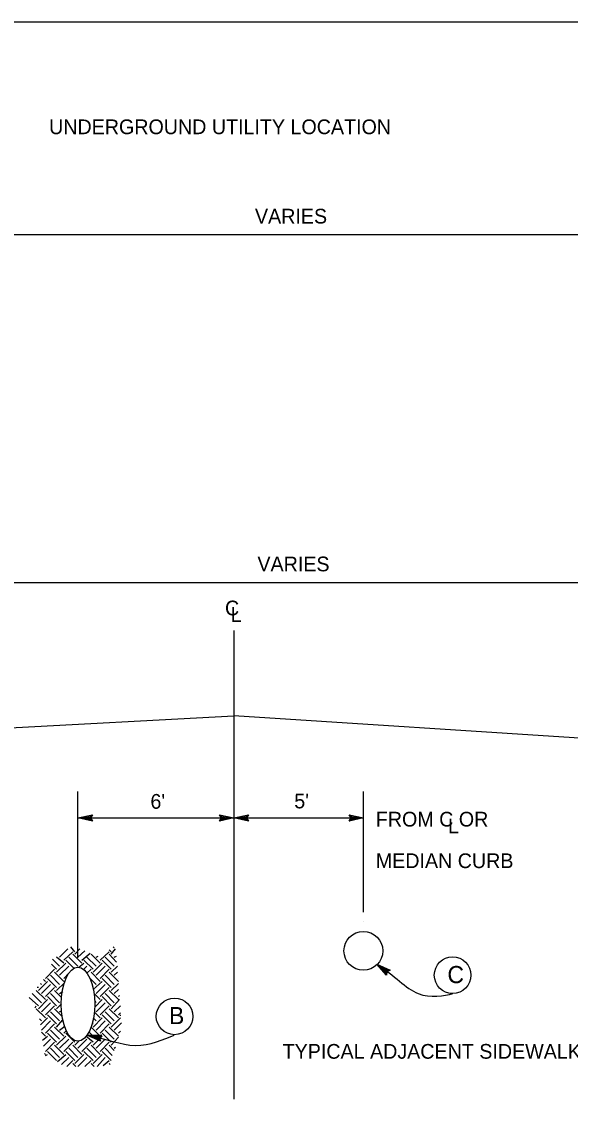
# Model space of a CAD drawing. Extents: x -119017 to -116080, y -104449 to -102845.
# Drawn here: x -118523 to -118299.2, y -103289.7 to -102845.2 of the extents above; entities that cross this region are included whole.
import ezdxf

# ---------------------------------------------------------------- set-up
doc = ezdxf.new("R2010")
doc.units = 0
for name, color, linetype in [('Default', 7, 'Continuous'), ('G-MARK', 7, 'Continuous'), ('G-TEXT', 7, 'Continuous'), ('Misc CnstDet(22)', 7, 'Continuous')]:
    doc.layers.add(name, color=color, linetype=linetype)

msp = doc.modelspace()

# ---------------------------------------------------------------- linework, layer by layer
at = {"layer": 'Default'}
msp.add_lwpolyline([(-119016.83, -102845.16), (-117223.08, -102845.16), (-117223.08, -104295.16), (-119016.83, -104295.16)], close=True, dxfattribs=at)
at = {"layer": 'G-MARK'}
for p, q in [((-118125.99, -102932.03), (-118744.83, -102932.03)), ((-118624.48, -103073.82), (-118229.29, -103073.82)), ((-118500.05, -103226.77), (-118500.05, -103158.98)), ((-118383.48, -103208.17), (-118383.48, -103158.98)), ((-118500.05, -103169.72), (-118436.44, -103169.72)), ((-118436.44, -103169.72), (-118383.48, -103169.72))]:
    msp.add_line(p, q, dxfattribs=at)
for centre in [(-118347.19, -103233.85), (-118460.65, -103250.64)]:
    msp.add_circle(centre, 7.47, dxfattribs=at)
for points in [[(-118378.15, -103229.35), (-118370.71, -103233.9), (-118362.03, -103244.65), (-118350.46, -103242.17), (-118347.15, -103241.34)], [(-118496.38, -103258.29), (-118488.53, -103259.53), (-118476.54, -103265.32), (-118464.96, -103259.95), (-118460.83, -103258.29)]]:
    msp.add_open_spline(points, degree=3, dxfattribs=at)
at = {"layer": 'G-TEXT'}
for points in [[(-118494.15, -103171.04), (-118500.05, -103169.72), (-118494.15, -103168.42), (-118494.36, -103168.76), (-118498.68, -103169.72), (-118494.36, -103170.69), (-118494.57, -103170.34), (-118497.33, -103169.73), (-118494.57, -103169.11), (-118494.78, -103169.46), (-118495.97, -103169.73), (-118494.77, -103170), (-118494.94, -103169.72), (-118494.15, -103168.42), (-118494.94, -103169.72)], [(-118442.3, -103168.41), (-118436.39, -103169.72), (-118442.3, -103171.03), (-118442.09, -103170.68), (-118437.76, -103169.73), (-118442.09, -103168.76), (-118441.88, -103169.1), (-118439.11, -103169.72), (-118441.88, -103170.34), (-118441.67, -103169.99), (-118440.47, -103169.72), (-118441.67, -103169.45), (-118441.51, -103169.72), (-118442.3, -103171.03), (-118441.51, -103169.72)], [(-118430.49, -103171.04), (-118436.39, -103169.72), (-118430.49, -103168.42), (-118430.7, -103168.76), (-118435.02, -103169.72), (-118430.7, -103170.69), (-118430.9, -103170.34), (-118433.67, -103169.73), (-118430.91, -103169.11), (-118431.12, -103169.46), (-118432.31, -103169.73), (-118431.11, -103170), (-118431.27, -103169.72), (-118430.49, -103168.42), (-118431.27, -103169.72)], [(-118389.38, -103168.41), (-118383.48, -103169.72), (-118389.39, -103171.03), (-118389.18, -103170.68), (-118384.85, -103169.73), (-118389.18, -103168.76), (-118388.97, -103169.1), (-118386.2, -103169.72), (-118388.97, -103170.34), (-118388.75, -103169.99), (-118387.56, -103169.72), (-118388.76, -103169.45), (-118388.6, -103169.72), (-118389.39, -103171.03), (-118388.6, -103169.72)], [(-118374.15, -103233.89), (-118378.15, -103229.35), (-118372.6, -103231.76), (-118372.98, -103231.92), (-118377.04, -103230.16), (-118374.11, -103233.48), (-118374.07, -103233.08), (-118375.95, -103230.95), (-118373.35, -103232.08), (-118373.73, -103232.24), (-118374.85, -103231.75), (-118374.04, -103232.67), (-118374.01, -103232.36), (-118372.6, -103231.76), (-118374.01, -103232.36)], [(-118490.83, -103260.71), (-118496.38, -103258.29), (-118490.33, -103258.13), (-118490.61, -103258.43), (-118495.04, -103258.55), (-118490.97, -103260.32), (-118491.11, -103259.94), (-118493.71, -103258.81), (-118490.88, -103258.73), (-118491.15, -103259.03), (-118492.38, -103259.07), (-118491.25, -103259.56), (-118491.36, -103259.26), (-118490.33, -103258.13), (-118491.36, -103259.26)]]:
    msp.add_lwpolyline(points, close=True, dxfattribs=at)
at = {"layer": 'Misc CnstDet(22)'}
for p, q in [((-118436.44, -103093.35), (-118436.44, -103284.34)), ((-118620.81, -103138), (-118436.44, -103128.08)), ((-118233.06, -103141.3), (-118436.44, -103128.08)), ((-118436.39, -103169.31), (-118436.39, -103169.31)), ((-118436.39, -103169.31), (-118436.39, -103169.31)), ((-118436.39, -103169.72), (-118436.39, -103169.72)), ((-118383.48, -103169.72), (-118383.48, -103169.72)), ((-118383.48, -103211.89), (-118383.48, -103211.89)), ((-118507.54, -103226.46), (-118504.24, -103223.15)), ((-118505.89, -103227.7), (-118502.17, -103224.39)), ((-118501.34, -103224.39), (-118503, -103222.33)), ((-118501.34, -103225.22), (-118499.28, -103223.15)), ((-118500.1, -103222.74), (-118500.1, -103222.74)), ((-118500.1, -103226.46), (-118497.21, -103223.98)), ((-118498.45, -103227.7), (-118495.14, -103224.81)), ((-118491.01, -103227.7), (-118487.29, -103224.39)), ((-118486.46, -103224.39), (-118487.29, -103223.57)), ((-118486.46, -103225.22), (-118484.81, -103223.15)), ((-118485.22, -103222.74), (-118485.63, -103222.33)), ((-118507.54, -103230.18), (-118510.44, -103227.29)), ((-118505.89, -103228.94), (-118508.78, -103226.46)), ((-118508.78, -103232.66), (-118505.06, -103228.94)), ((-118501.76, -103231.01), (-118505.06, -103227.7)), ((-118500.1, -103230.18), (-118503.82, -103226.46)), ((-118498.45, -103228.94), (-118502.17, -103225.22)), ((-118499.69, -103230.6), (-118497.62, -103228.94)), ((-118493.9, -103231.42), (-118497.62, -103227.7)), ((-118492.66, -103230.18), (-118496.38, -103226.46)), ((-118491.01, -103228.94), (-118494.73, -103225.22)), ((-118493.9, -103232.66), (-118490.18, -103228.94)), ((-118492.66, -103226.46), (-118491.83, -103226.05)), ((-118486.46, -103231.42), (-118490.18, -103227.7)), ((-118485.22, -103230.18), (-118488.94, -103226.46)), ((-118484.39, -103228.53), (-118487.29, -103225.22)), ((-118485.22, -103226.46), (-118484.39, -103226.05)), ((-118513.33, -103235.14), (-118509.61, -103231.42)), ((-118511.26, -103230.18), (-118511.26, -103230.18)), ((-118508.78, -103231.42), (-118510.85, -103229.35)), ((-118505.89, -103236.38), (-118509.61, -103232.66)), ((-118507.54, -103233.9), (-118503.82, -103230.18)), ((-118505.89, -103235.14), (-118503.82, -103233.08)), ((-118500.05, -103230.49), (-118500.05, -103230.49)), ((-118497.62, -103231.42), (-118496.38, -103230.18)), ((-118496.38, -103233.08), (-118494.73, -103231.42)), ((-118491.01, -103236.38), (-118494.73, -103232.66)), ((-118492.66, -103233.9), (-118488.94, -103230.18)), ((-118491.01, -103235.14), (-118487.29, -103231.42)), ((-118483.57, -103236.38), (-118487.29, -103232.66)), ((-118486.46, -103232.66), (-118483.98, -103230.18)), ((-118485.22, -103233.9), (-118483.98, -103232.66)), ((-118516.22, -103240.1), (-118512.5, -103236.38)), ((-118514.98, -103237.62), (-118515.4, -103237.21)), ((-118514.98, -103241.34), (-118511.26, -103237.62)), ((-118513.33, -103236.38), (-118514.16, -103235.56)), ((-118508.78, -103238.86), (-118512.5, -103235.14)), ((-118507.54, -103237.62), (-118511.26, -103233.9)), ((-118508.78, -103240.1), (-118505.48, -103236.8)), ((-118505.06, -103235.56), (-118505.06, -103235.14)), ((-118492.66, -103237.62), (-118495.14, -103235.14)), ((-118493.9, -103239.69), (-118490.18, -103236.38)), ((-118492.66, -103241.34), (-118488.94, -103237.62)), ((-118486.46, -103238.86), (-118490.18, -103235.14)), ((-118485.22, -103237.62), (-118488.94, -103233.9)), ((-118486.46, -103240.1), (-118483.57, -103237.21)), ((-118483.57, -103235.14), (-118483.57, -103235.14)), ((-118514.98, -103245.06), (-118518.7, -103241.34)), ((-118513.33, -103243.82), (-118517.05, -103240.1)), ((-118516.22, -103238.86), (-118516.64, -103238.86)), ((-118513.33, -103242.58), (-118509.61, -103238.86)), ((-118508.78, -103246.3), (-118512.5, -103242.58)), ((-118507.54, -103245.06), (-118511.26, -103241.34)), ((-118506.72, -103243), (-118509.61, -103240.1)), ((-118507.54, -103241.34), (-118506.3, -103240.52)), ((-118491.01, -103243.82), (-118493.49, -103241.34)), ((-118491.01, -103242.58), (-118487.29, -103238.86)), ((-118486.46, -103246.3), (-118490.18, -103242.58)), ((-118485.22, -103245.06), (-118488.94, -103241.34)), ((-118483.57, -103243.82), (-118487.29, -103240.1)), ((-118485.22, -103241.34), (-118483.57, -103239.69)), ((-118483.57, -103242.58), (-118483.15, -103242.17)), ((-118516.22, -103246.3), (-118519.94, -103243)), ((-118518.7, -103245.06), (-118518.7, -103245.06)), ((-118517.46, -103247.13), (-118517.05, -103246.3)), ((-118516.22, -103247.54), (-118512.5, -103243.82)), ((-118514.98, -103248.78), (-118511.26, -103245.06)), ((-118513.33, -103250.02), (-118509.61, -103246.3)), ((-118508.78, -103247.54), (-118506.72, -103245.48)), ((-118493.07, -103246.72), (-118490.18, -103243.82)), ((-118492.66, -103245.06), (-118493.07, -103244.24)), ((-118492.66, -103248.78), (-118488.94, -103245.06)), ((-118491.01, -103250.02), (-118487.29, -103246.3)), ((-118486.46, -103247.54), (-118483.15, -103243.82)), ((-118485.22, -103248.78), (-118482.74, -103246.3)), ((-118513.33, -103251.26), (-118517.05, -103247.54)), ((-118515.4, -103254.16), (-118512.5, -103251.26)), ((-118508.78, -103253.74), (-118512.5, -103250.02)), ((-118507.54, -103252.5), (-118511.26, -103248.78)), ((-118506.72, -103250.44), (-118509.61, -103247.54)), ((-118507.54, -103248.78), (-118506.72, -103248.37)), ((-118492.66, -103252.5), (-118493.9, -103251.26)), ((-118493.9, -103254.98), (-118490.18, -103251.26)), ((-118491.01, -103251.26), (-118493.49, -103248.78)), ((-118486.46, -103253.74), (-118490.18, -103250.02)), ((-118485.22, -103252.5), (-118488.94, -103248.78)), ((-118483.57, -103251.26), (-118487.29, -103247.54)), ((-118486.46, -103254.98), (-118482.74, -103251.26)), ((-118483.57, -103250.02), (-118482.74, -103249.2)), ((-118482.74, -103250.44), (-118482.74, -103250.02)), ((-118514.98, -103252.5), (-118515.81, -103251.68)), ((-118514.98, -103256.22), (-118511.26, -103252.5)), ((-118513.33, -103257.47), (-118509.61, -103253.74)), ((-118505.89, -103258.71), (-118509.61, -103254.98)), ((-118508.78, -103254.98), (-118506.3, -103252.09)), ((-118507.54, -103256.22), (-118505.48, -103254.57)), ((-118491.01, -103258.71), (-118494.73, -103254.98)), ((-118493.9, -103253.74), (-118494.31, -103253.74)), ((-118492.66, -103256.22), (-118488.94, -103252.5)), ((-118491.01, -103257.47), (-118487.29, -103253.74)), ((-118483.57, -103258.71), (-118487.29, -103254.98)), ((-118485.22, -103256.22), (-118482.33, -103253.33)), ((-118513.33, -103258.71), (-118514.98, -103257.05)), ((-118514.57, -103260.36), (-118512.5, -103258.71)), ((-118514.16, -103262.84), (-118511.26, -103259.95)), ((-118508.78, -103261.19), (-118512.5, -103257.47)), ((-118507.54, -103259.95), (-118511.26, -103256.22)), ((-118508.78, -103262.43), (-118505.06, -103258.71)), ((-118507.54, -103263.67), (-118503.82, -103259.95)), ((-118505.89, -103257.47), (-118505.06, -103256.64)), ((-118501.34, -103261.19), (-118505.06, -103257.47)), ((-118500.1, -103263.67), (-118496.38, -103259.95)), ((-118493.9, -103261.19), (-118496.8, -103258.71)), ((-118492.66, -103259.95), (-118495.55, -103257.05)), ((-118493.9, -103262.43), (-118490.18, -103258.71)), ((-118492.66, -103263.67), (-118488.94, -103259.95)), ((-118486.46, -103261.19), (-118490.18, -103257.47)), ((-118485.22, -103259.95), (-118488.94, -103256.22)), ((-118486.46, -103262.43), (-118483.57, -103259.12)), ((-118483.57, -103257.47), (-118482.74, -103256.64)), ((-118513.33, -103264.91), (-118509.61, -103261.19)), ((-118507.54, -103267.39), (-118511.26, -103263.67)), ((-118505.89, -103266.15), (-118509.61, -103262.43)), ((-118505.89, -103264.91), (-118502.17, -103261.19)), ((-118500.1, -103267.39), (-118503.82, -103263.67)), ((-118498.45, -103266.15), (-118502.17, -103262.43)), ((-118501.34, -103262.43), (-118499.69, -103260.77)), ((-118498.45, -103264.91), (-118494.73, -103261.19)), ((-118492.66, -103267.39), (-118496.38, -103263.67)), ((-118491.01, -103266.15), (-118494.73, -103262.43)), ((-118491.01, -103264.91), (-118487.29, -103261.19)), ((-118486.05, -103266.56), (-118488.94, -103263.67)), ((-118485.22, -103264.49), (-118487.29, -103262.43)), ((-118485.22, -103263.67), (-118484.81, -103263.25)), ((-118513.33, -103266.15), (-118513.74, -103265.73)), ((-118513.33, -103266.56), (-118512.5, -103266.15)), ((-118508.78, -103268.63), (-118512.5, -103264.91)), ((-118511.26, -103267.39), (-118511.26, -103267.39)), ((-118508.37, -103269.04), (-118505.06, -103266.15)), ((-118506.72, -103270.28), (-118503.82, -103267.39)), ((-118501.34, -103268.63), (-118505.06, -103264.91)), ((-118504.65, -103271.11), (-118502.17, -103268.63)), ((-118501.34, -103269.87), (-118497.62, -103266.15)), ((-118500.1, -103271.11), (-118496.38, -103267.39)), ((-118493.9, -103268.63), (-118497.62, -103264.91)), ((-118497.21, -103271.11), (-118494.73, -103268.63)), ((-118493.9, -103269.87), (-118490.18, -103266.15)), ((-118492.25, -103271.11), (-118488.94, -103267.39)), ((-118486.46, -103268.63), (-118490.18, -103264.91)), ((-118489.77, -103270.69), (-118487.29, -103268.63)), ((-118500.93, -103271.11), (-118502.17, -103269.87)), ((-118493.49, -103271.11), (-118494.73, -103269.87)), ((-118486.87, -103270.28), (-118487.29, -103269.87))]:
    msp.add_line(p, q, dxfattribs=at)
msp.add_circle((-118383.61, -103223.94), 7.91, dxfattribs=at)
msp.add_ellipse((-118500.07, -103245.68), major_axis=(0, 15.07), ratio=0.454353, dxfattribs=at)

# ---------------------------------------------------------------- texts
for s, height, p in [('UNDERGROUND UTILITY LOCATION', 6, (-118511.84, -102890.97)), ('VARIES', 6, (-118427.83, -102927.4)), ('VARIES', 6, (-118426.83, -103069.2)), ('C', 6, (-118440.06, -103087.15)), ('L', 6, (-118437.73, -103089.8)), ("6'", 6, (-118470.49, -103165.99)), ("5'", 6, (-118411.8, -103165.83)), ('FROM C OR', 6, (-118378.52, -103173.24)), ('L', 6, (-118349.08, -103176.02)), ('MEDIAN CURB', 6, (-118378.52, -103190.19)), ('C', 7, (-118349.3, -103237.1)), ('B', 7, (-118462.92, -103253.82)), ('TYPICAL ADJACENT SIDEWALK SECTION', 6, (-118416.55, -103267.91))]:
    msp.add_text(s, height=height, dxfattribs=at).set_placement(p)

doc.saveas('drawing.dxf')
